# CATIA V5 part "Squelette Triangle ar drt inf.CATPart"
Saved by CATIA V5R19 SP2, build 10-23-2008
Part number: Squelette Triangle ar drt inf
Bounding box of the stored display mesh (mm): x 296.231 to 352.225, y -118.317 to -30.006, z 29.944 to 66.841
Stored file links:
  D:\Mes Documents\ressource\CATIA\Ensemble Catia\Voiture_Telecommmande\SchemaCinematiqueFinal\Squelette Triangle ar drt inf.CATPart
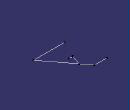
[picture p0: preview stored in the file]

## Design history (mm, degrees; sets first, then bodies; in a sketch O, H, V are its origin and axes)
AxisSystem1: origin (0, 0, 0), X (1, 0, 0), Y (0, 1, 0), Z (0, 0, 1)
Body1 (main body)
  Line1 to Line5: stored without definition
  Point1 to Point3: stored without definition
